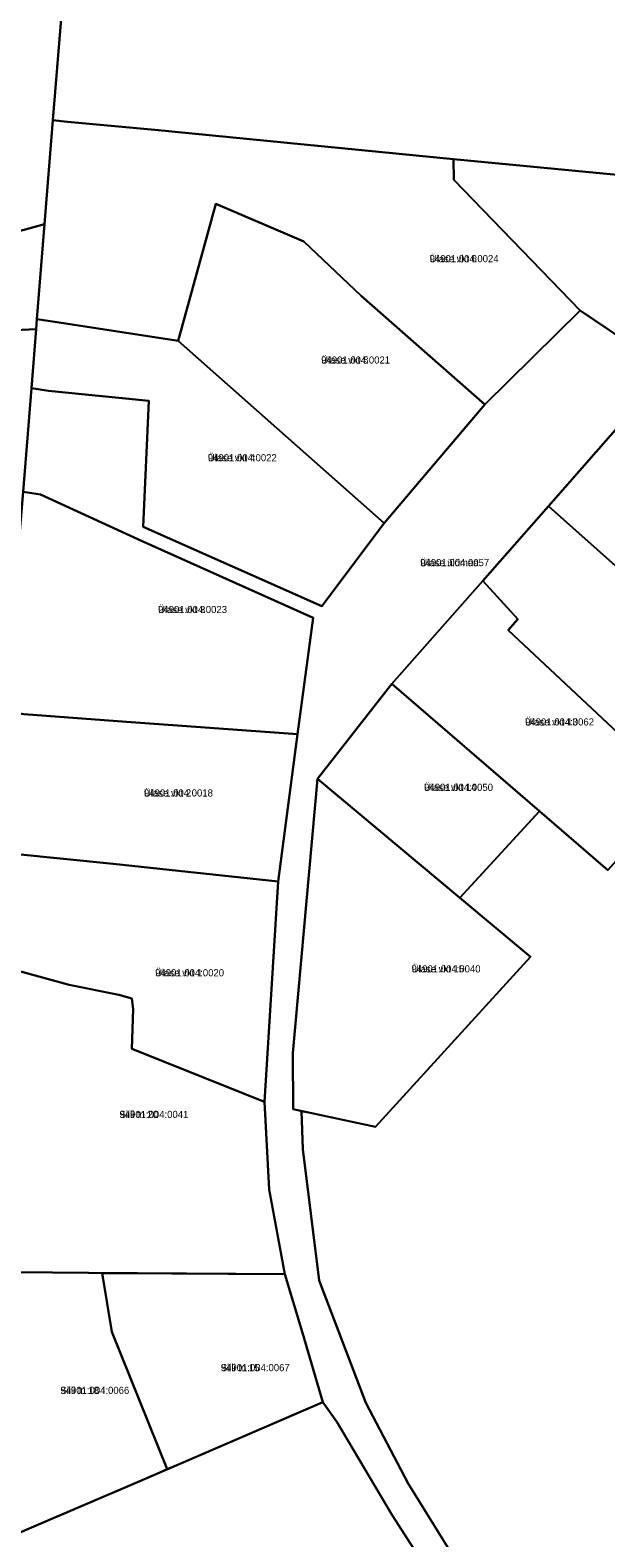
# Model space of a CAD drawing. Extents: x 647845 to 668483, y 6445298 to 6473683.
# Drawn here: x 653312.8 to 653434, y 6468125.6 to 6468442.7 of the extents above; entities that cross this region are included whole.
import ezdxf

# ---------------------------------------------------------------- set-up
doc = ezdxf.new("R2010")
doc.units = 0
for name, color, linetype in [('L_AADRESS', 7, 'Continuous'), ('PIIR', 7, 'Continuous'), ('TUNNUS', 7, 'Continuous')]:
    doc.layers.add(name, color=color, linetype=linetype)

msp = doc.modelspace()

# ---------------------------------------------------------------- linework, layer by layer
at = {"layer": 'PIIR'}
for points in [[(653710.59, 6468385.69), (653555.14, 6468400.78), (653531.19, 6468403.11), (653478.45, 6468408.19), (653472.23, 6468408.79), (653401.93, 6468415.57), (653339.11, 6468421.73), (653320.73, 6468423.39), (653317.65, 6468423.77), (653333.23, 6468613.76), (653334.45, 6468623.86), (653340.7, 6468623.38), (653833.65, 6468592.05)], [(653333.23, 6468613.76), (653317.65, 6468423.77), (653315.86, 6468401.88), (653306.73, 6468399.38), (653309.61, 6468433.07), (653272.15, 6468435.7), (653245.98, 6468438.76), (653221.36, 6468442.23), (653196.46, 6468444.93)], [(653403.26, 6468119.5), (653392.35, 6468137.07), (653383.49, 6468153.98), (653373.63, 6468179.74), (653370.23, 6468207.36), (653369.96, 6468215.36), (653371.77, 6468214.97), (653385.51, 6468212.03), (653418.07, 6468247.81), (653403.25, 6468260.18), (653419.97, 6468278.47), (653434.4, 6468266.03), (653449.41, 6468282.78), (653466.98, 6468302.4), (653482.8, 6468320.05), (653499.74, 6468338.96), (653515.81, 6468356.89), (653552.93, 6468398.32), (653555.14, 6468400.78), (653710.59, 6468385.69)], [(653400.18, 6468113.08), (653388.98, 6468130.4), (653377.36, 6468150.02), (653374.44, 6468154.13), (653370.16, 6468168.76), (653366.4, 6468181.08), (653363.15, 6468198.86), (653362.17, 6468217.34), (653365.02, 6468263.65), (653369.06, 6468294.6), (653372.42, 6468319.12), (653336.41, 6468335.22), (653315.04, 6468345.02), (653311.36, 6468345.59), (653313.1, 6468367.38), (653316.68, 6468366.82), (653337.82, 6468364.76), (653336.62, 6468338.23), (653374.21, 6468321.52), (653387.35, 6468339.02), (653408.49, 6468363.98), (653428.57, 6468383.73), (653440.81, 6468375.49)], [(653438.46, 6468361.42), (653421.92, 6468342.6), (653408.1, 6468326.89), (653388.93, 6468305.24), (653373.32, 6468285.27), (653368.1, 6468227.55), (653368.15, 6468215.75), (653369.96, 6468215.36), (653370.23, 6468207.36), (653373.63, 6468179.74), (653383.49, 6468153.98), (653392.35, 6468137.07), (653403.26, 6468119.5)]]:
    msp.add_lwpolyline(points, dxfattribs=at)
for points in [[(653428.57, 6468383.73), (653408.49, 6468363.98), (653382.47, 6468386.83), (653370.41, 6468398.22), (653351.91, 6468406.13), (653344.01, 6468377.35), (653318.01, 6468381.37), (653314.26, 6468381.94), (653315.86, 6468401.88), (653317.65, 6468423.77), (653320.73, 6468423.39), (653339.11, 6468421.73), (653401.93, 6468415.57), (653402.01, 6468411.24)], [(653401.93, 6468415.57), (653472.23, 6468408.79), (653472.42, 6468405.73), (653450.28, 6468380.77), (653443.99, 6468376), (653440.81, 6468375.49), (653428.57, 6468383.73), (653402.01, 6468411.24)], [(653370.41, 6468398.22), (653382.47, 6468386.83), (653408.49, 6468363.98), (653387.35, 6468339.02), (653344.01, 6468377.35), (653351.91, 6468406.13)], [(653314.09, 6468379.81), (653309.7, 6468379.61), (653302.98, 6468379.48), (653287.35, 6468365.99), (653283.98, 6468369.15), (653265.27, 6468353.94), (653256.56, 6468378.73), (653255.22, 6468382.49), (653269.02, 6468387.04), (653306.73, 6468399.38), (653315.86, 6468401.88), (653314.26, 6468381.94)], [(653302.98, 6468379.48), (653309.7, 6468379.61), (653314.09, 6468379.81), (653313.1, 6468367.38), (653311.36, 6468345.59), (653309.38, 6468321.5), (653303.5, 6468321.5), (653272.78, 6468353.43), (653287.35, 6468365.99)], [(653344.01, 6468377.35), (653387.35, 6468339.02), (653374.21, 6468321.52), (653336.62, 6468338.23), (653337.82, 6468364.76), (653316.68, 6468366.82), (653313.1, 6468367.38), (653314.09, 6468379.81), (653314.26, 6468381.94), (653318.01, 6468381.37)], [(653438.46, 6468361.42), (653468.77, 6468333.14), (653482.8, 6468320.05), (653466.98, 6468302.4), (653452.61, 6468315.22), (653421.92, 6468342.6)], [(653336.41, 6468335.22), (653372.42, 6468319.12), (653369.06, 6468294.6), (653333.11, 6468297.24), (653311.54, 6468298.83), (653307.69, 6468299.4), (653309.38, 6468321.5), (653311.36, 6468345.59), (653315.04, 6468345.02)], [(653421.92, 6468342.6), (653452.61, 6468315.22), (653466.98, 6468302.4), (653449.41, 6468282.78), (653435.43, 6468295.87), (653413.4, 6468316.5), (653415.47, 6468318.82), (653408.1, 6468326.89)], [(653408.1, 6468326.89), (653415.47, 6468318.82), (653413.4, 6468316.5), (653435.43, 6468295.87), (653449.41, 6468282.78), (653434.4, 6468266.03), (653419.97, 6468278.47), (653388.93, 6468305.24)], [(653419.97, 6468278.47), (653403.25, 6468260.18), (653373.32, 6468285.27), (653388.93, 6468305.24)], [(653333.11, 6468297.24), (653369.06, 6468294.6), (653365.02, 6468263.65), (653330.28, 6468267.38), (653309.43, 6468269.48), (653305.31, 6468270.08), (653307.23, 6468294.07), (653307.54, 6468297.44), (653307.69, 6468299.4), (653311.54, 6468298.83)], [(653403.25, 6468260.18), (653418.07, 6468247.81), (653385.51, 6468212.03), (653368.15, 6468215.75), (653368.1, 6468227.55), (653373.32, 6468285.27)], [(653330.28, 6468267.38), (653365.02, 6468263.65), (653362.17, 6468217.34), (653334.23, 6468228.47), (653334.52, 6468236.78), (653334.27, 6468239.01), (653331.51, 6468239.8), (653321.07, 6468241.91), (653307.52, 6468245.61), (653303.66, 6468246.76), (653303.71, 6468247.34), (653305.31, 6468270.08), (653309.43, 6468269.48)], [(653331.51, 6468239.8), (653334.27, 6468239.01), (653334.52, 6468236.78), (653334.23, 6468228.47), (653362.17, 6468217.34), (653363.15, 6468198.86), (653366.4, 6468181.08), (653325.13, 6468181.33), (653302.33, 6468181.54), (653298.37, 6468181.66), (653299.5, 6468197.03), (653303.66, 6468246.76), (653307.52, 6468245.61), (653321.07, 6468241.91)], [(653302.33, 6468181.54), (653325.13, 6468181.33), (653328.02, 6468181.3), (653330.05, 6468168.95), (653341.68, 6468140.04), (653339.51, 6468139.11), (653334.92, 6468137.13), (653313.65, 6468128.03), (653308.82, 6468125.87), (653302.01, 6468144.98), (653296.72, 6468159.3), (653298.02, 6468176.9), (653298.37, 6468181.66)], [(653330.73, 6468181.31), (653366.4, 6468181.08), (653370.16, 6468168.76), (653374.44, 6468154.13), (653344.06, 6468141.06), (653341.68, 6468140.04), (653330.05, 6468168.95), (653328.02, 6468181.3)], [(653334.92, 6468137.13), (653374.44, 6468154.13), (653377.36, 6468150.02), (653388.98, 6468130.4), (653400.18, 6468113.08), (653357.06, 6468095.35), (653331.09, 6468084.64), (653328.31, 6468083.51), (653324.38, 6468091.38), (653316.88, 6468109.53), (653308.82, 6468125.87), (653313.65, 6468128.03)]]:
    msp.add_lwpolyline(points, close=True, dxfattribs=at)

# ---------------------------------------------------------------- texts
at = {"layer": 'L_AADRESS'}
for s, p in [('Ülase vkt 6', (653396.89, 6468393.88)), ('Ülase vkt 5', (653374.06, 6468372.57)), ('Ülase vkt 4', (653350.23, 6468352.02)), ('Ülase üldmaa', (653394.91, 6468329.96)), ('Ülase vkt 3', (653339.76, 6468320.1)), ('Ülase vkt 13', (653416.96, 6468296.46)), ('Ülase vkt 14', (653395.71, 6468282.71)), ('Ülase vkt 2', (653336.79, 6468281.52)), ('Ülase vkt 1', (653339.14, 6468243.71)), ('Ülase vkt 15', (653393.09, 6468244.53)), ('Siili tn 20', (653331.63, 6468213.92)), ('Siili tn 15', (653352.95, 6468160.67)), ('Siili tn 18', (653319.2, 6468155.89))]:
    msp.add_text(s, height=1.5, dxfattribs=at).set_placement(p)
at = {"layer": 'TUNNUS'}
for s, p in [('94901:004:0024', (653396.89, 6468393.88)), ('94901:004:0021', (653374.06, 6468372.57)), ('94901:004:0022', (653350.23, 6468352.02)), ('94901:004:0057', (653394.91, 6468329.96)), ('94901:004:0023', (653339.76, 6468320.1)), ('94901:004:0062', (653416.96, 6468296.46)), ('94901:004:0018', (653336.79, 6468281.52)), ('94901:004:0050', (653395.71, 6468282.71)), ('94901:004:0020', (653339.14, 6468243.71)), ('94901:004:0040', (653393.09, 6468244.53)), ('94901:004:0041', (653331.63, 6468213.92)), ('94901:004:0067', (653352.95, 6468160.67)), ('94901:004:0066', (653319.2, 6468155.89))]:
    msp.add_text(s, height=1.5, dxfattribs=at).set_placement(p)

doc.saveas('drawing.dxf')
